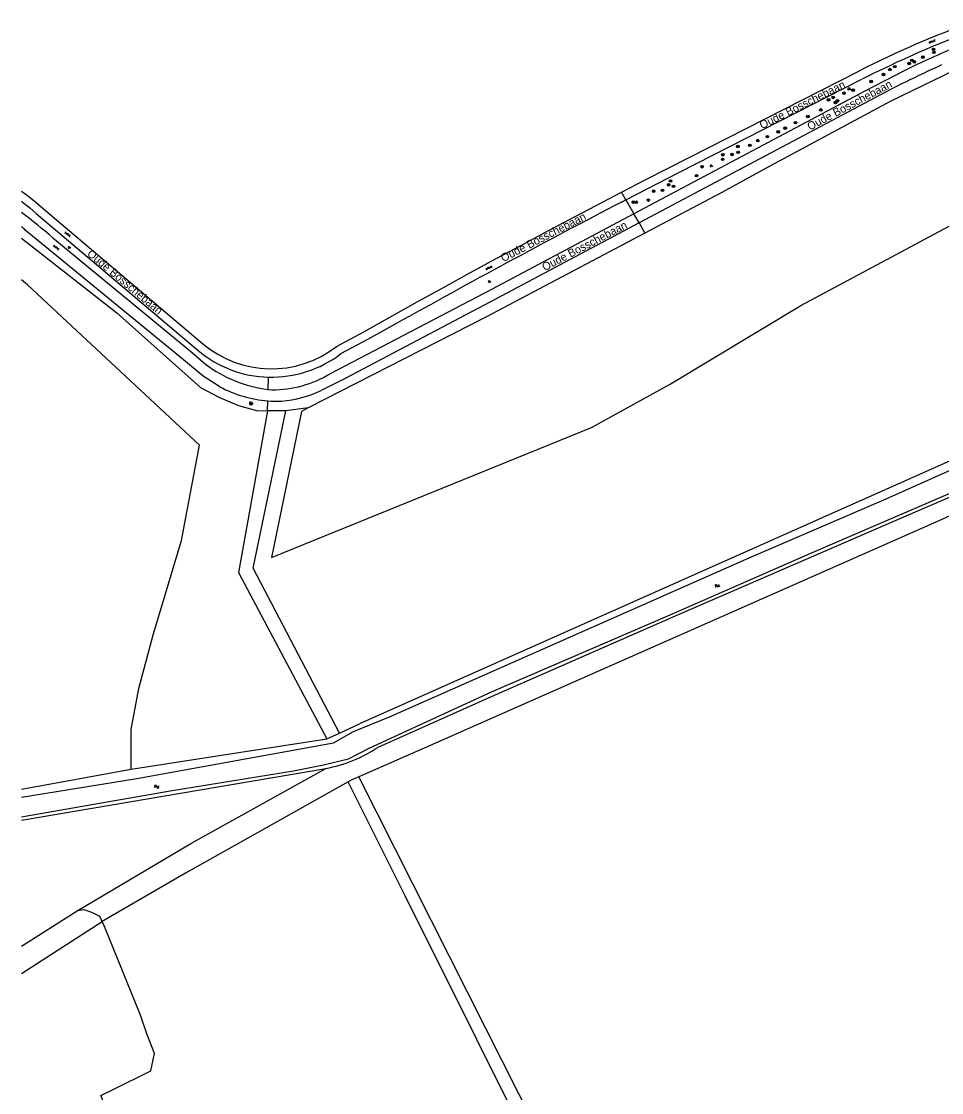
# Model space of a CAD drawing. Extents: x 137000 to 140001, y 403500 to 406000.
# Drawn here: x 137000 to 137287.5, y 405221.8 to 405556.5 of the extents above; entities that cross this region are included whole.
import ezdxf

# ---------------------------------------------------------------- set-up
doc = ezdxf.new("R2010")
doc.units = 0
for name, color, linetype in [('gg-afsc-draadraster', 7, 'Continuous'), ('gg-anno-openbare ruimte label', 7, 'Continuous'), ('gg-knt-bronhoudergrens', 7, 'Continuous'), ('gg-knt-onverhard', 7, 'Continuous'), ('gg-knt-verharding', 7, 'Continuous'), ('gg-kntw-bovenkant insteek waterloop', 7, 'Continuous'), ('gg-kntw-waterlijn', 7, 'Continuous'), ('gt-grn-groengrens', 7, 'Continuous'), ('gt-grn-weggrens', 7, 'Continuous'), ('gt-symb-boom', 7, 'Continuous'), ('gt-symb-gesloten verharding', 7, 'Continuous'), ('gt-symb-groenvak', 7, 'Continuous'), ('gt-symb-lichtmast', 7, 'Continuous'), ('gt-symb-watersymbool', 7, 'Continuous')]:
    doc.layers.add(name, color=color, linetype=linetype)

# ---------------------------------------------------------------- blocks, each defined once
blk = doc.blocks.new('gt0-BOOM')
at = {"layer": 'gt-symb-boom'}
for radius in [0.4, 0.2]:
    blk.add_circle((0, 0), radius, dxfattribs=at)
blk = doc.blocks.new('gt0-GESVH1')
at = {"layer": 'gt-symb-gesloten verharding'}
for p, q in [((-0.99, -0.26), (0.01, 0.24)), ((0.01, -0.26), (-0.99, 0.24)), ((0.01, 0.24), (1.01, -0.26)), ((1.01, 0.24), (0.01, -0.26))]:
    blk.add_line(p, q, dxfattribs=at)
blk = doc.blocks.new('gt0-GRVAK')
at = {"layer": 'gt-symb-groenvak'}
for p, q in [((-0.11, 0.19), (-0.23, 0.24)), ((-0.18, 0.15), (0.09, 0.15)), ((-0.09, 0.21), (-0.16, 0.32)), ((-0.05, 0.21), (-0.05, 0.39)), ((0, 0.21), (0.06, 0.32)), ((0.01, 0.19), (0.13, 0.24)), ((0.26, -0.05), (0.2, 0.06)), ((0.3, -0.05), (0.3, 0.13)), ((0.35, -0.05), (0.41, 0.06)), ((-0.24, -0.23), (-0.36, -0.18)), ((-0.32, -0.26), (-0.05, -0.26)), ((-0.23, -0.21), (-0.29, -0.09)), ((-0.18, -0.2), (-0.18, -0.02)), ((-0.14, -0.21), (-0.07, -0.09)), ((-0.12, -0.23), (0, -0.18)), ((0.24, -0.07), (0.12, -0.02)), ((0.17, -0.11), (0.44, -0.11)), ((0.37, -0.07), (0.49, -0.02))]:
    blk.add_line(p, q, dxfattribs=at)
blk = doc.blocks.new('gt0-LMAST')
at = {"layer": 'gt-symb-lichtmast'}
for p, q in [((-0.18, 0.17), (-0.45, 0.44)), ((-0.01, 0.25), (-0.01, 0.62)), ((0.17, 0.17), (0.44, 0.44)), ((-0.26, 0), (-0.63, 0)), ((-0.18, -0.18), (-0.45, -0.45)), ((-0.01, -0.25), (-0.01, -0.63)), ((0.44, -0.45), (0.17, -0.18)), ((0.24, 0), (0.62, 0))]:
    blk.add_line(p, q, dxfattribs=at)
blk.add_circle((-0.01, 0), 0.25, dxfattribs=at)
blk = doc.blocks.new('gt0-WA')
at = {"layer": 'gt-symb-watersymbool'}
for centre, start, end in [((-0.32, 0.02), 28.0725, 151.9275), ((0.43, 0.42), 208.0725, 331.9275), ((-0.32, -0.43), 28.0725, 151.9275), ((0.43, -0.03), 208.0725, 331.9275)]:
    blk.add_arc(centre, 0.425, start, end, dxfattribs=at)

msp = doc.modelspace()

# ---------------------------------------------------------------- linework, layer by layer
at = {"layer": 'gg-afsc-draadraster'}
for points in [[(137294.87, 405542.8), (137271.61, 405531.49), (137233.82, 405511.24), (137218.83, 405503.02), (137194.79, 405490.33)], [(137178.16, 405429.62), (137202.46, 405443.05), (137243.58, 405467.72), (137289.68, 405492.36), (137313.38, 405505.54)], [(137194.79, 405490.33), (137145.11, 405464.1), (137089.6, 405435.72)]]:
    msp.add_lwpolyline(points, dxfattribs=at)
at = {"layer": 'gg-knt-bronhoudergrens'}
for p, q in [((137000, 405267.59), (137017.46, 405278.59)), ((137000, 405259.01), (137025.26, 405275.25))]:
    msp.add_line(p, q, dxfattribs=at)
for points in [[(137034.3, 405322.88), (137034.3, 405335.23), (137036.66, 405348.06), (137041.16, 405364.87), (137049.98, 405394.29), (137055.63, 405424.05), (137001.85, 405474.12), (137000, 405475.72)], [(137089.6, 405435.72), (137087.53, 405434.63), (137078.18, 405388.97), (137178.16, 405429.62)], [(137025.26, 405275.25), (137024.55, 405276.79), (137022.01, 405278.06), (137019.57, 405278.91), (137017.46, 405278.59)], [(137102.74, 405016.71), (137094.83, 405039.32), (137090.21, 405053.58), (137081.2, 405076.03), (137051.04, 405154.94), (137042.46, 405175.81), (137035.46, 405196.11), (137029.45, 405209.55), (137024.85, 405220.93), (137028.88, 405222.84), (137040.46, 405228.56), (137041.61, 405233.99), (137039.18, 405240.14), (137037.17, 405246), (137025.96, 405273.7), (137025.26, 405275.25)]]:
    msp.add_lwpolyline(points, dxfattribs=at)
at = {"layer": 'gg-knt-onverhard'}
for points in [[(137076.91, 405434.75), (137067.86, 405384.31), (137095.47, 405332.33)], [(137099.37, 405334.11), (137072.38, 405385.64), (137082.64, 405434.75)], [(137226.18, 405083.36), (137221.18, 405080.82), (137209.61, 405103.57), (137119.86, 405283.33), (137102.11, 405318.87)], [(137181.54, 405169.7), (137145.02, 405242), (137105.39, 405320.45)]]:
    msp.add_lwpolyline(points, dxfattribs=at)
at = {"layer": 'gg-knt-verharding'}
for p, q in [((137265.07, 405531.79), (137192.99, 405493.48)), ((137187.49, 405500), (137188.88, 405500.71)), ((137077.1, 405441.49), (137078.25, 405441.38))]:
    msp.add_line(p, q, dxfattribs=at)
for points in [[(137187.52, 405503.1), (137195.09, 405507.03), (137208.66, 405513.98), (137261.86, 405541.04)], [(137275.83, 405541.04), (137263.52, 405534.62), (137191.38, 405496.32)], [(137188.88, 405500.71), (137205.65, 405509.35), (137262.64, 405538.39)], [(137000, 405503.43), (137002.27, 405501.77), (137004.46, 405500), (137006.13, 405498.53), (137056.6, 405455.81)], [(137098.48, 405454.91), (137106.97, 405459.52), (137123.62, 405468.8), (137131.85, 405473.34), (137140.09, 405477.86), (137148.35, 405482.34), (137156.63, 405486.8), (137164.93, 405491.23), (137173.23, 405495.63), (137181.56, 405500), (137187.52, 405503.1)], [(137000, 405500.25), (137000.34, 405500), (137002.5, 405498.28), (137004.57, 405496.45), (137055.08, 405453.74)], [(137191.38, 405496.32), (137146.86, 405472.71), (137096.45, 405446.39)], [(137192.99, 405493.48), (137148.38, 405469.76), (137101.11, 405444.88), (137093.69, 405441.15)], [(137062.02, 405442.28), (137056.83, 405445.64), (137050.67, 405450.73), (137007.47, 405486.18), (137001.22, 405491.29)], [(137009.84, 405488.86), (137052.79, 405453.4), (137057.51, 405449.42)], [(137116.82, 405461.85), (137108.33, 405457.14), (137099.75, 405452.61)]]:
    msp.add_lwpolyline(points, dxfattribs=at)
for centre, radius, start, end in [((137400.75, 405267.95), 306.38, 109.6683, 116.9579), ((137408.84, 405251.47), 322.01, 111.37, 117.0008), ((137410.84, 405265.26), 307.06, 112.6186, 116.085), ((137438.62, 405207.75), 367.59, 114.2729, 118.173), ((138362.08, 403239.88), 2547.12, 117.46111, 119.26777), ((136875.82, 405332.33), 206.06, 49.4292, 52.9408), ((136962.58, 405444.14), 60.96, 50.6638, 52.1312), ((137078.12, 405480.98), 35.68, 229.7816, 268.5519), ((137078.09, 405481.2), 33.27, 229.7491, 307.7998), ((137081.5, 405480.54), 39.29, 232.3676, 263.5725), ((137078.12, 405480.98), 35.67, 268.5514, 307.3239), ((137078.37, 405476.51), 35.13, 269.8134, 300.9738), ((137080.11, 405476.65), 38.84, 242.2319, 265.4051), ((137077.56, 405476.5), 38.86, 275.5627, 294.5228), ((137080.1, 405476.62), 38.81, 265.4118, 271.8106)]:
    msp.add_arc(centre, radius, start, end, dxfattribs=at)
at = {"layer": 'gg-kntw-bovenkant insteek waterloop'}
for p, q in [((137099.37, 405334.11), (137105.65, 405336.97)), ((137034.3, 405322.88), (137095.47, 405332.33)), ((137095.47, 405332.33), (137099.37, 405334.11)), ((137000, 405306.91), (137095.11, 405323.09)), ((137000, 405316.6), (137034.3, 405322.88))]:
    msp.add_line(p, q, dxfattribs=at)
for points in [[(137447.49, 405486.38), (137360.13, 405449.63), (137292.11, 405419.97), (137105.65, 405336.97)], [(137365.18, 405440.17), (137273.18, 405400.5), (137205.2, 405371.06), (137146.74, 405345.45), (137111.37, 405329.67)]]:
    msp.add_lwpolyline(points, dxfattribs=at)
msp.add_arc((137087.4, 405365.49), 43.1, 280.3026, 303.7926, dxfattribs=at)
at = {"layer": 'gg-kntw-waterlijn'}
for points in [[(137000, 405314.13), (137036.1, 405319.98), (137097.52, 405331.05), (137103.71, 405334.6), (137114.98, 405339.2), (137227.35, 405388.89), (137270.21, 405407.33), (137309.13, 405424.66), (137338.12, 405437.85), (137361.49, 405447.63), (137380.92, 405455.72), (137418.05, 405472.04), (137448.31, 405484.97), (137459.65, 405486.79), (137503.64, 405488.8), (137542.35, 405489.91), (137584.14, 405492.39), (137601.37, 405491.37), (137609.61, 405490.64), (137636.47, 405489.03), (137676.27, 405487.07), (137698.23, 405485.17)], [(137000, 405308.01), (137001.21, 405308.21), (137046.44, 405316.08), (137085.02, 405322.36), (137094.38, 405324.25), (137102.15, 405326.04), (137108.68, 405329.36), (137146.85, 405346.97), (137201.93, 405370.71), (137246.65, 405390.31), (137320.43, 405422.12), (137339.68, 405430.84), (137364.62, 405442.09), (137395.42, 405455.43), (137428.3, 405470.2), (137443.97, 405476.66), (137453.77, 405479.88), (137464.62, 405481.17), (137515.77, 405483.28), (137548.36, 405484.2), (137571.92, 405485.32), (137584.2, 405486.16), (137596.47, 405484.97), (137637.62, 405482.9)]]:
    msp.add_lwpolyline(points, dxfattribs=at)
at = {"layer": 'gt-grn-groengrens'}
for p, q in [((137188.88, 405500.71), (137191.38, 405496.32)), ((137192.99, 405493.48), (137194.79, 405490.33)), ((137077.1, 405441.49), (137077.21, 405445.31)), ((137076.91, 405434.75), (137077, 405437.93)), ((137082.64, 405434.75), (137076.91, 405434.75)), ((137089.6, 405435.72), (137082.64, 405434.75))]:
    msp.add_line(p, q, dxfattribs=at)
for points in [[(137000, 405488.69), (137029.79, 405465.46), (137055.97, 405442.07), (137061.66, 405439.07), (137067.8, 405436.46), (137073.41, 405434.94), (137076.91, 405434.75)], [(137358.75, 405432.97), (137285.75, 405400.01), (137125.83, 405329.46), (137105.39, 405320.45)], [(137017.46, 405278.59), (137052.92, 405299.6), (137095.11, 405323.09)], [(137102.11, 405318.87), (137051.3, 405290.33), (137025.26, 405275.25)], [(137105.39, 405320.45), (137103.19, 405319.48), (137102.11, 405318.87)]]:
    msp.add_lwpolyline(points, dxfattribs=at)
at = {"layer": 'gt-grn-weggrens'}
for p, q in [((137188.88, 405500.71), (137187.52, 405503.1)), ((137192.99, 405493.48), (137191.38, 405496.32))]:
    msp.add_line(p, q, dxfattribs=at)

# ---------------------------------------------------------------- block references
at = {"layer": 'gt-symb-boom'}
for p in [(137284.97, 405547.74), (137285.12, 405546.81), (137277.39, 405543.31), (137278.21, 405544.29), (137279, 405543.83), (137281.68, 405545.29), (137269.36, 405539.86), (137271.33, 405541.41), (137272.91, 405542.33), (137265.5, 405537.68), (137253.64, 405532.72), (137257.01, 405534.05), (137258.6, 405535.37), (137259.87, 405534.99), (137252.17, 405531.95), (137254.34, 405531.13), (137254.98, 405531.67), (137245.73, 405526.74), (137249.79, 405528.8), (137238.62, 405523.09), (137241.86, 405524.82), (137230.07, 405519.23), (137233.07, 405520.44), (137236.44, 405521.95), (137223.83, 405517.38), (137227.59, 405517.75), (137219.1, 405513.37), (137219.18, 405514.81), (137222.02, 405514.89), (137223.96, 405515.54), (137212.68, 405511.05), (137202.79, 405506.59), (137210.96, 405508.28), (137197.54, 405503.41), (137200.32, 405503.68), (137202.22, 405505.4), (137203.76, 405504.94), (137191.21, 405500.01), (137192.14, 405499.96), (137195.89, 405500.64)]:
    msp.add_blockref('gt0-BOOM', p, dxfattribs=at)
at = {"layer": 'gt-symb-gesloten verharding'}
for p, rotation in [((137284.52, 405550.17), 22.024845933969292), ((137014.4, 405489.97), -38.01566048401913), ((137010.86, 405485.8), -38.01566048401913), ((137146.06, 405479.45), 27.974729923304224)]:
    msp.add_blockref('gt0-GESVH1', p, dxfattribs=dict(at, rotation=rotation))
at = {"layer": 'gt-symb-groenvak'}
for p in [(137215.52, 405511.34), (137014.93, 405485.83), (137146.22, 405475.21)]:
    msp.add_blockref('gt0-GRVAK', p, dxfattribs=at)
at = {"layer": 'gt-symb-lichtmast'}
msp.add_blockref('gt0-LMAST', (137071.74, 405437.1), dxfattribs=at)
at = {"layer": 'gt-symb-watersymbool', "rotation": 24.515070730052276}
msp.add_blockref('gt0-WA', (137217.37, 405380.14), dxfattribs=at)
at = {"layer": 'gt-symb-watersymbool'}
msp.add_blockref('gt0-WA', (137042.2, 405317.38), dxfattribs=at)

# ---------------------------------------------------------------- texts
at = {"layer": 'gg-anno-openbare ruimte label'}
for rotation, p in [(26.6, (137231.41, 405522.76)), (28, (137246.36, 405522.32)), (27.3, (137150.58, 405481.23)), (27.7, (137163.51, 405478.4)), (320.1, (137020.32, 405483.52))]:
    msp.add_text('Oude Bosschebaan', height=2.5, rotation=rotation, dxfattribs=at).set_placement(p)

doc.saveas('drawing.dxf')
